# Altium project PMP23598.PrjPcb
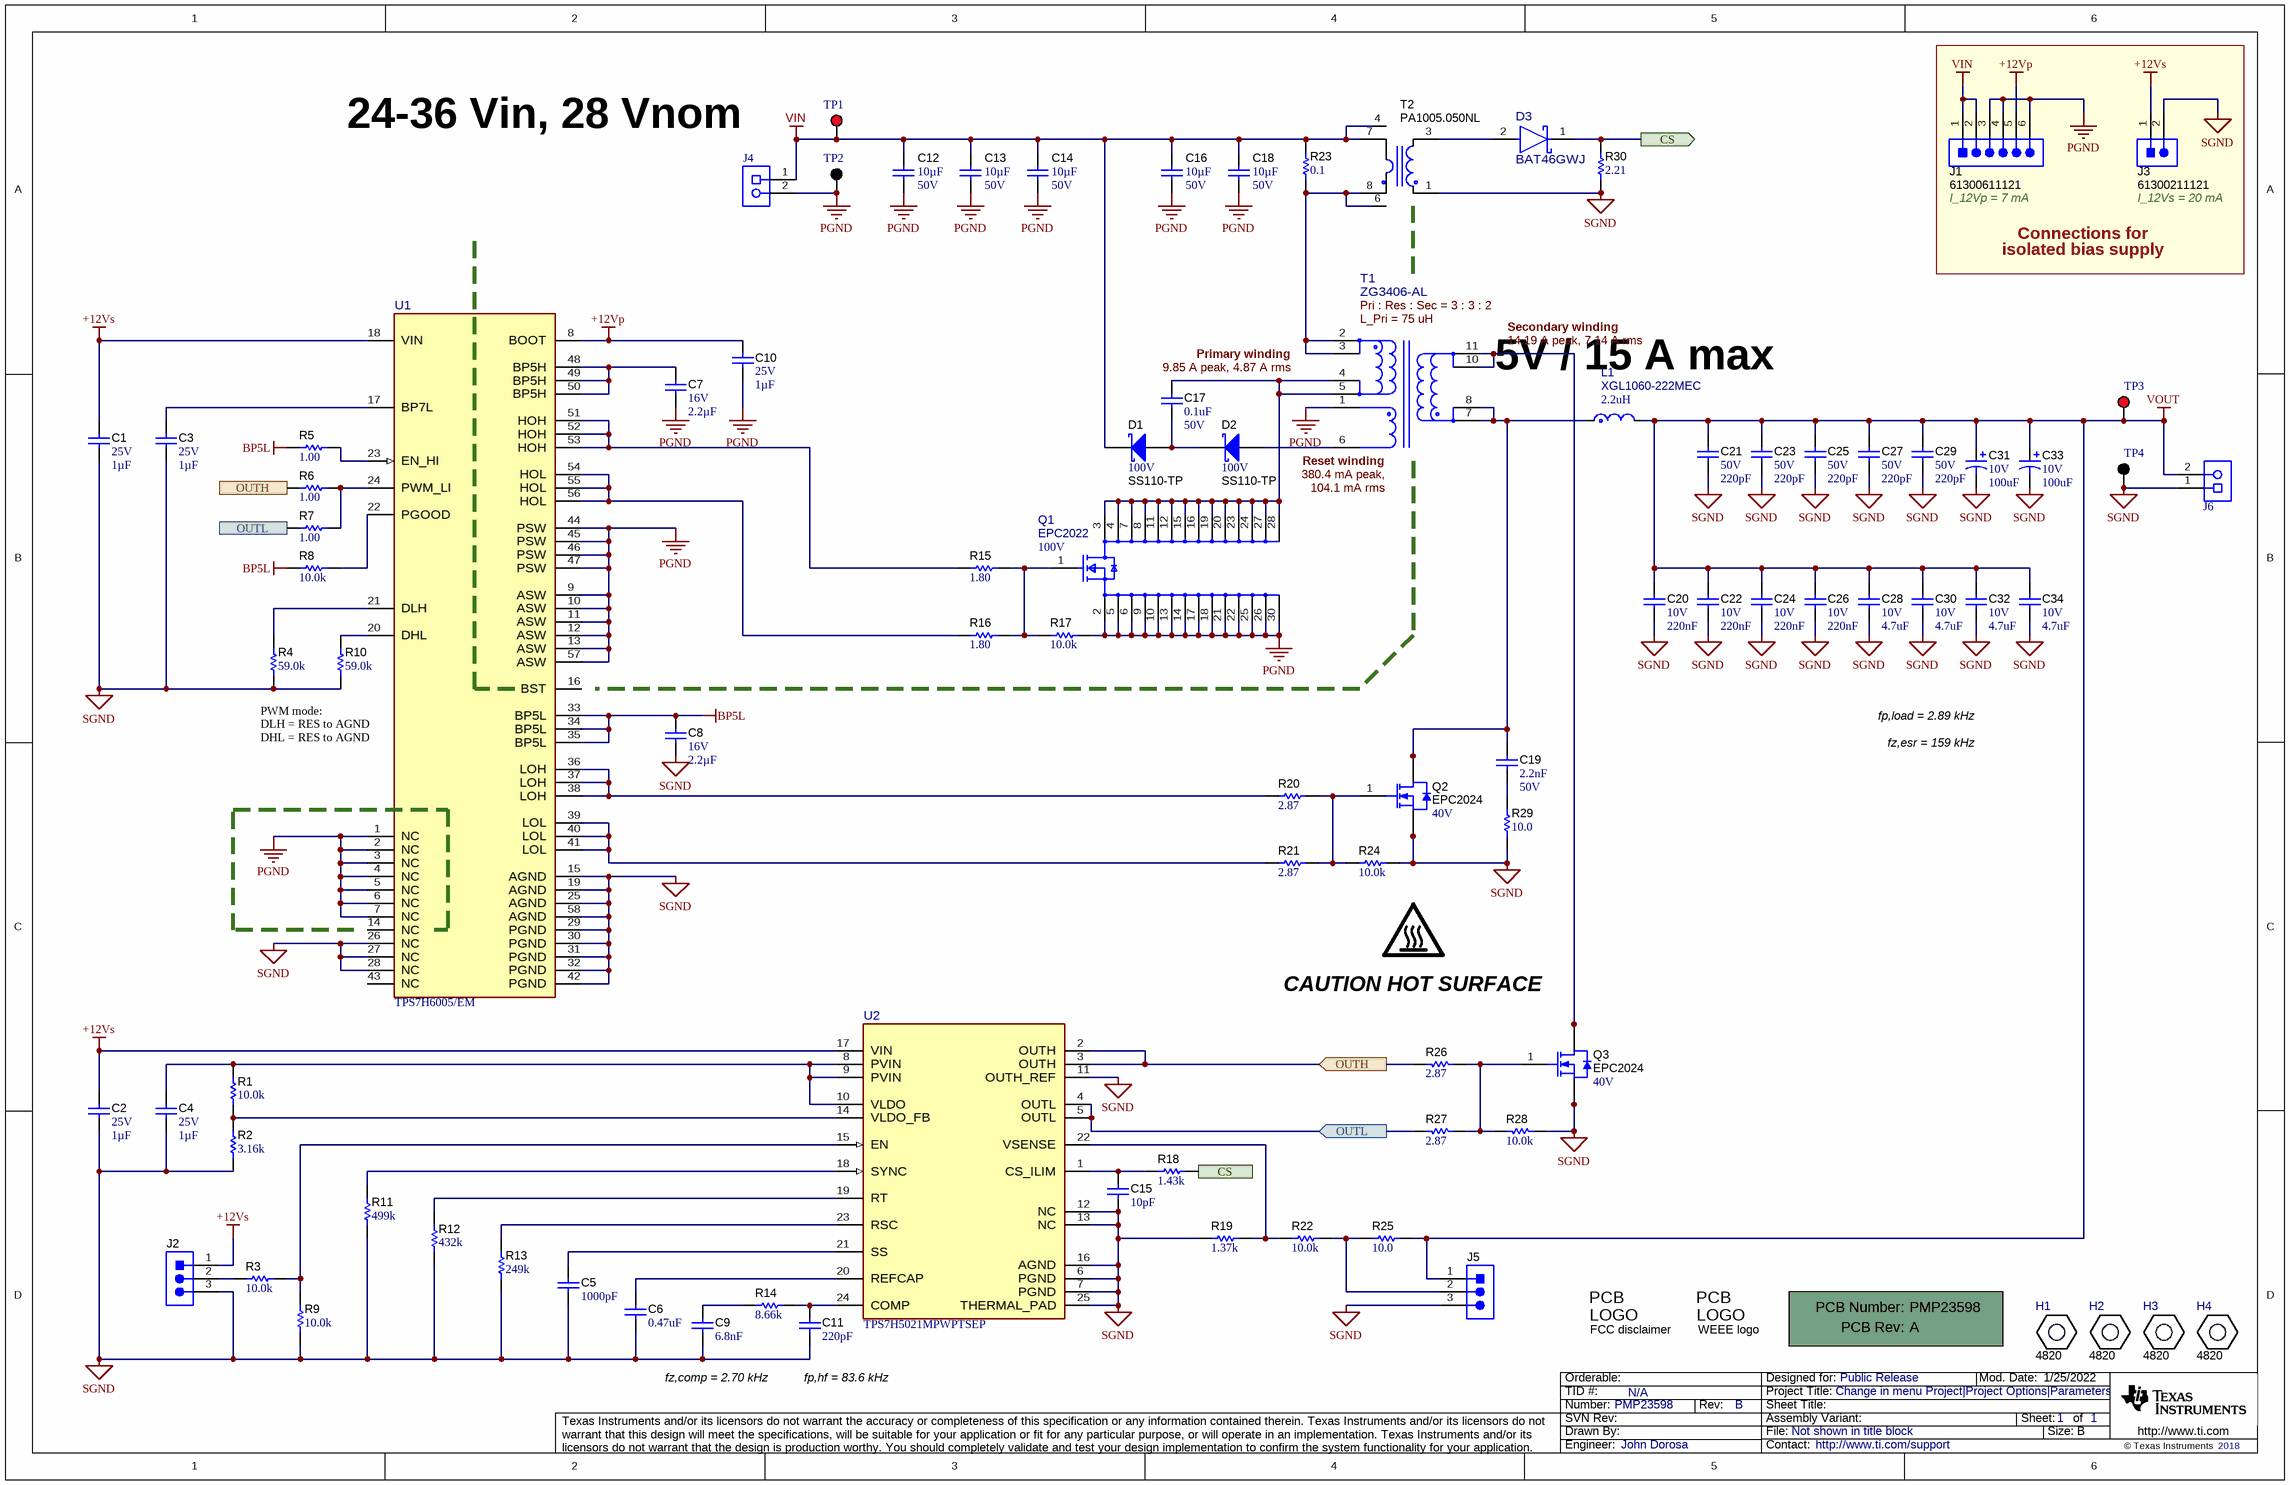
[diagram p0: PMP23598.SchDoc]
TID: N/A; TechSupport: http://www.ti.com/support; SCH_Rev: B; PRJ_Title: Change in menu Project|Project Options|Parameters; PRJ_Number: PMP23598; PRJ_Engineer: John Dorosa; PRJ_Customer: Public Release; PCB_Rev: A; PCB_Layout: John Dorosa; CopyrightYear: 2018
1 sheet, 93 parts. Net scope: flat (ports and power ports of the same name join across sheets).
Board file: PMP23598.PcbDoc

## Sheet PMP23598.SchDoc
size 431 x 279 mm; Date: Not shown in title block; ApprovedBy: Not shown in title block; CheckedBy: Not shown in title block; Author: Not shown in title block; CompanyName: Not shown in title block; Engineer: Not shown in title block; Organization: Not shown in title block; Address1: Not shown in title block; Address2: Not shown in title block; Address3: Not shown in title block; Address4: Not shown in title block; DocumentNumber: 1; Revision: Use project parameter SCH_Rev; SheetNumber: 1; SheetTotal: 1; PageSetup: Record=PageOptions¦CenterHorizontal=True¦CenterVertical=True¦PrintScale=1.00¦XCorrection=1.00¦YCorrection=1.00¦PrintKind=0¦BorderSize=5000000¦LeftOffset=0¦BottomOffset=0¦Orientation=2¦PaperLength=1000¦PaperWidth=1000¦Scale=100¦PaperSource=15¦PrintQuality=600¦MediaType=1¦DitherType=10¦PaperKind=Letter¦PrintScaleMode=1

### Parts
!PCB1  Printed Circuit Board  (value not drawn)  (mechanical)
C1  VDC_V: 25V  Cap_F: 1µF  [0603_HV]  (hidden comment: GRM188R71E105KA12D)
C2  VDC_V: 25V  Cap_F: 1µF  [0603_HV]  (hidden comment: GRM188R71E105KA12D)
C3  VDC_V: 25V  Cap_F: 1µF  [0603_HV]  (hidden comment: GRM188R71E105KA12D)
C4  VDC_V: 25V  Cap_F: 1µF  [0603_HV]  (hidden comment: GRM188R71E105KA12D)
C5  value 1000pF  [0603_HV]  (hidden comment: GRM188R71E102KA01D)
C6  value 0.47uF  [0603_HV]  (hidden comment: GCM188R71C474KA55D)
C7  VDC_V: 16V  Cap_F: 2.2µF  [0603_HV]  (hidden comment: GRM188Z71C225KE43)
C8  VDC_V: 16V  Cap_F: 2.2µF  [0603_HV]  (hidden comment: GRM188Z71C225KE43)
C9  Cap_F: 6.8nF  [0603_HV]  (hidden comment: GRM188R71E682KA01D)
C10  VDC_V: 25V  Cap_F: 1µF  [0603_HV]  (hidden comment: GRM188R71E105KA12D)
C11  Cap_F: 220pF  [0603_HV]  (hidden comment: GRM188R71H221KA01D)
C12  ValueDisplayed: 10µF  VDC_V: 50V  [1210_270]  (hidden comment: GCM32EL8EH106KA07L)
C13  ValueDisplayed: 10µF  VDC_V: 50V  [1210_270]  (hidden comment: GCM32EL8EH106KA07L)
C14  ValueDisplayed: 10µF  VDC_V: 50V  [1210_270]  (hidden comment: GCM32EL8EH106KA07L)
C15  ValueDisplayed: 10pF  [0603_HV]  (hidden comment: GCM1885C2A100JA16D)
C16  ValueDisplayed: 10µF  VDC_V: 50V  [1210_270]  (hidden comment: GCM32EL8EH106KA07L)
C17  value 0.1uF  VDC_V: 50V  [0805_HV]  (hidden comment: GRM21BR71H104KA01L)
C18  ValueDisplayed: 10µF  VDC_V: 50V  [1210_270]  (hidden comment: GCM32EL8EH106KA07L)
C19  Cap_F: 2.2nF  VDC_V: 50V  [0603_HV]  (hidden comment: GRM188R71H222KA01D)
C20  Value2: 10V  Cap_F: 220nF  [0805_HV]  (hidden comment: GRM216R71A224KC01D)
C21  VDC_V: 50V  ValueDisplayed: 220pF  [0402]  (hidden comment: GRM155R71H221KA01D)
C22  Value2: 10V  Cap_F: 220nF  [0805_HV]  (hidden comment: GRM216R71A224KC01D)
C23  VDC_V: 50V  ValueDisplayed: 220pF  [0402]  (hidden comment: GRM155R71H221KA01D)
C24  Value2: 10V  Cap_F: 220nF  [0805_HV]  (hidden comment: GRM216R71A224KC01D)
C25  VDC_V: 50V  ValueDisplayed: 220pF  [0402]  (hidden comment: GRM155R71H221KA01D)
C26  Value2: 10V  Cap_F: 220nF  [0805_HV]  (hidden comment: GRM216R71A224KC01D)
C27  VDC_V: 50V  ValueDisplayed: 220pF  [0402]  (hidden comment: GRM155R71H221KA01D)
C28  VDC_V: 10V  ValueDisplayed: 4.7uF  [1210]  (hidden comment: C1210C475K8RACTU)
C29  VDC_V: 50V  ValueDisplayed: 220pF  [0402]  (hidden comment: GRM155R71H221KA01D)
C30  VDC_V: 10V  ValueDisplayed: 4.7uF  [1210]  (hidden comment: C1210C475K8RACTU)
C31  VDC_V: 10V  ValueDisplayed: 100uF  [6032-15]  (hidden comment: T495U107K010ZTE150)
C32  VDC_V: 10V  ValueDisplayed: 4.7uF  [1210]  (hidden comment: C1210C475K8RACTU)
C33  VDC_V: 10V  ValueDisplayed: 100uF  [6032-15]  (hidden comment: T495U107K010ZTE150)
C34  VDC_V: 10V  ValueDisplayed: 4.7uF  [1210]  (hidden comment: C1210C475K8RACTU)
D1  SS110-TP  value 100V  [SMA]
D2  SS110-TP  value 100V  [SMA]
D3  BAT46GWJ  [FP-BAT46GWJ_SOD-123-MFG]
H1  4820  [KEYSTONE_4820]
H2  4820  [KEYSTONE_4820]
H3  4820  [KEYSTONE_4820]
H4  4820  [KEYSTONE_4820]
J1  61300611121  [WURTH_61300611121]
J2  61300311121  [WURTH_61300311121]  (value not drawn)
J3  61300211121  [WURTH_61300211121]
J4  ED120/2DS  [On-Shore_ED120_2DS]  (value not drawn)
J5  61300311121  [WURTH_61300311121]  (value not drawn)
J6  ED120/2DS  [On-Shore_ED120_2DS]  (value not drawn)
L1  XGL1060-222MEC  value 2.2uH  [FP-XGL1060-222MEC_SMD2-MFG]
Logo1  CAUTION HOT SURFACE  [IEC_HotSurface_Small]  (no BOM)
Logo2  FCC disclaimer  [FCC_disclaimer]  (no BOM)
Logo3  WEEE logo  [WEEE_Minimum]  (no BOM)
Q1  EPC2022  VdsMax_V: 100V  [FP-EPC2022_LGA30-MFG]
Q2  EPC2024  value 40V  [EPC2023]
Q3  EPC2024  value 40V  [EPC2023]
R1  ValueDisplayed: 10.0k  [0603_HV]  (hidden comment: CRCW060310K0FKEA)
R2  ValueDisplayed: 3.16k  [0603_HV]  (hidden comment: CRCW06033K16FKEA)
R3  ValueDisplayed: 10.0k  [0603_HV]  (hidden comment: CRCW060310K0FKEA)
R4  ValueDisplayed: 59.0k  [0603_HV]  (hidden comment: CRCW060359K0FKEA)
R5  ValueDisplayed: 1.00  [0603_HV]  (hidden comment: CRCW06031R00FKEA)
R6  ValueDisplayed: 1.00  [0603_HV]  (hidden comment: CRCW06031R00FKEA)
R7  ValueDisplayed: 1.00  [0603_HV]  (hidden comment: CRCW06031R00FKEA)
R8  ValueDisplayed: 10.0k  [0603_HV]  (hidden comment: RG1608P-103-B-T5)
R9  ValueDisplayed: 10.0k  [0603_HV]  (hidden comment: CRCW060310K0FKEA)
R10  ValueDisplayed: 59.0k  [0603_HV]  (hidden comment: CRCW060359K0FKEA)
R11  ValueDisplayed: 499k  [0603_HV]  (hidden comment: CRCW0603499KFKEA)
R12  ValueDisplayed: 432k  [0603_HV]  (hidden comment: CRCW0603432KFKEA)
R13  ValueDisplayed: 249k  [0603_HV]  (hidden comment: CRCW0603249KFKEA)
R14  ValueDisplayed: 8.66k  [0603_HV]  (hidden comment: CRCW06038K66FKEA)
R15  ValueDisplayed: 1.80  [0603_HV]  (hidden comment: CRCW06031R80FKEA)
R16  ValueDisplayed: 1.80  [0603_HV]  (hidden comment: CRCW06031R80FKEA)
R17  ValueDisplayed: 10.0k  [0603_HV]  (hidden comment: CRCW060310K0FKEA)
R18  ValueDisplayed: 1.43k  [0603_HV]  (hidden comment: CRCW06031K43FKEA)
R19  ValueDisplayed: 1.37k  [0603_HV]  (hidden comment: CRCW06031K37FKEA)
R20  ValueDisplayed: 2.87  [0603_HV]  (hidden comment: CRCW06032R87FKEA)
R21  ValueDisplayed: 2.87  [0603_HV]  (hidden comment: CRCW06032R87FKEA)
R22  ValueDisplayed: 10.0k  [0603_HV]  (hidden comment: CRCW060310K0FKEA)
R23  ValueDisplayed: 0.1  [1210]  (hidden comment: ERJ14RSJR10U)
R24  ValueDisplayed: 10.0k  [0603_HV]  (hidden comment: CRCW060310K0FKEA)
R25  ValueDisplayed: 10.0  [0603_HV]  (hidden comment: CRCW060310R0FKEA)
R26  ValueDisplayed: 2.87  [0603_HV]  (hidden comment: CRCW06032R87FKEA)
R27  ValueDisplayed: 2.87  [0603_HV]  (hidden comment: CRCW06032R87FKEA)
R28  ValueDisplayed: 10.0k  [0603_HV]  (hidden comment: CRCW060310K0FKEA)
R29  ValueDisplayed: 10.0  [1218]  (hidden comment: CRCW121810R0FKEK)
R30  ValueDisplayed: 2.21  [0805_HV1]  (hidden comment: CRCW08052R21FKEA)
T1  ZG3406-AL  [FP-ZG3406-AL_SMT_XFRMR_23MM37_20MM83-MFG]
T2  PA1005.050NL  [P82xx]
TP1  5010  [Keystone5010]  (value not drawn)
TP2  5011  [Keystone5011]  (value not drawn)
TP3  5010  [Keystone5010]  (value not drawn)
TP4  5011  [Keystone5011]  (value not drawn)
U1  TPS7H6005/EM  [DCA0056M-MFG]
U2  TPS7H5021MPWPTSEP  [PWP0024R-MFG]

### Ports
CS (in), CS (out), OUTH (in), OUTL (in)

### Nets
+12Vp: C10.1 J1.5 U1.8(BOOT)
+12Vs: C1.1 C2.1 J2.1 J3.1 U1.18(VIN) U2.17(VIN)
BP5L: C8.2 R5.2 R8.1 U1.33(BP5L) U1.34(BP5L) U1.35(BP5L)
PGND: C7.1 C10.2 C12.2 C13.2 C14.2 C16.2 C18.2 J1.3 J1.4 J1.6 J4.2 Q1.2(Source) Q1.5(Source) Q1.6(Source) Q1.9(Source) Q1.10(Source) Q1.13(Source) Q1.14(Source) Q1.17(Source) Q1.18(Source) Q1.21(Source) Q1.22(Source) Q1.25(Source) Q1.26(Source) Q1.30(Substrate) R17.2 T1.1 TP2.1 U1.1(NC) U1.2(NC) U1.3(NC) U1.4(NC) U1.5(NC) U1.6(NC) U1.7(NC) U1.9(ASW) U1.10(ASW) U1.11(ASW) U1.12(ASW) U1.13(ASW) U1.44(PSW) U1.45(PSW) U1.46(PSW) U1.47(PSW) U1.57(ASW)
SGND: C1.2 C2.2 C3.1 C4.2 C5.1 C6.2 C8.1 C9.2 C11.2 C15.2 C20.1 C21.2 C22.1 C23.2 C24.1 C25.2 C26.1 C27.2 C28.2 C29.2 C30.2 C31.2(-) C32.2 C33.2(-) C34.2 J2.3 J3.2 J5.3 J6.1 Q2.2(S) Q2.5(S) Q2.6(S) Q2.9(S) Q2.10(S) Q2.13(S) Q2.14(S) Q2.17(S) Q2.18(S) Q2.21(S) Q2.22(S) Q2.25(S) Q2.26(S) Q2.29(S) Q2.30(Substrate) Q3.2(S) Q3.5(S) Q3.6(S) Q3.9(S) Q3.10(S) Q3.13(S) Q3.14(S) Q3.17(S) Q3.18(S) Q3.21(S) Q3.22(S) Q3.25(S) Q3.26(S) Q3.29(S) Q3.30(Substrate) R2.2 R4.1 R9.1 R10.1 R11.1 R12.1 R13.1 R19.2 R24.2 R28.1 R29.1 R30.1 T2.1 TP4.1 U1.15(AGND) U1.19(AGND) U1.25(AGND) U1.26(NC) U1.27(NC) U1.28(NC) U1.29(PGND) U1.30(PGND) U1.31(PGND) U1.32(PGND) U1.42(PGND) U1.58(AGND) U2.6(PGND) U2.7(PGND) U2.11(OUTH_REF) U2.12(NC) U2.13(NC) U2.16(AGND) U2.25(THERMAL_PAD)
VIN: C12.1 C13.1 C14.1 C16.1 C18.1 D1.1(K) J1.1 J1.2 J4.1 R23.2 T2.4 T2.7 TP1.1
VOUT: C20.2 C21.1 C22.2 C23.1 C24.2 C25.1 C26.2 C27.1 C28.1 C29.1 C30.1 C31.1(+) C32.1 C33.1(+) C34.1 J5.1 J6.2 L1.2 R25.2 TP3.1
CS: D3.1(CATHODE) R18.2 R30.2 ; port CS
OUTH: R6.2 R26.2 U2.2(OUTH) U2.3(OUTH) ; port OUTH
OUTL: R7.2 R27.2 U2.4(OUTL) U2.5(OUTL) ; port OUTL
NetC3_2: C3.2 U1.17(BP7L)
NetC4_1: C4.1 R1.2 U2.8(PVIN) U2.9(PVIN) U2.10(VLDO)
NetC5_2: C5.2 U2.21(SS)
NetC6_1: C6.1 U2.20(REFCAP)
NetC7_2: C7.2 U1.48(BP5H) U1.49(BP5H) U1.50(BP5H)
NetC9_1: C9.1 R14.2
NetC11_1: C11.1 R14.1 U2.24(COMP)
NetC15_1: C15.1 R18.1 U2.1(CS_ILIM)
NetC17_1: C17.1 D1.2(A) D2.1(K)
NetC17_2: C17.2 Q1.3(Drain) Q1.4(Drain) Q1.7(Drain) Q1.8(Drain) Q1.11(Drain) Q1.12(Drain) Q1.15(Drain) Q1.16(Drain) Q1.19(Drain) Q1.20(Drain) Q1.23(Drain) Q1.24(Drain) Q1.27(Drain) Q1.28(Drain) T1.4 T1.5
NetC19_1: C19.1 L1.1 Q2.3(D) Q2.4(D) Q2.7(D) Q2.8(D) Q2.11(D) Q2.12(D) Q2.15(D) Q2.16(D) Q2.19(D) Q2.20(D) Q2.23(D) Q2.24(D) Q2.27(D) Q2.28(D) T1.7 T1.8
NetC19_2: C19.2 R29.2
NetD2_2: D2.2(A) T1.6
NetD3_2: D3.2(ANODE) T2.3
NetJ2_2: J2.2 R3.2
NetJ5_2: J5.2 R22.2 R25.1
NetQ1_1: Q1.1(Gate) R15.2 R16.2 R17.1
NetQ2_1: Q2.1(G) R20.2 R21.2 R24.1
NetQ3_1: Q3.1(G) R26.1 R27.1 R28.2
NetQ3_3: Q3.3(D) Q3.4(D) Q3.7(D) Q3.8(D) Q3.11(D) Q3.12(D) Q3.15(D) Q3.16(D) Q3.19(D) Q3.20(D) Q3.23(D) Q3.24(D) Q3.27(D) Q3.28(D) T1.10 T1.11
NetR1_1: R1.1 R2.1 U2.14(VLDO_FB)
NetR3_1: R3.1 R9.2 U2.15(EN)
NetR4_2: R4.2 U1.21(DLH)
NetR5_1: R5.1 U1.23(EN_HI)
NetR6_1: R6.1 R7.1 U1.24(PWM_LI)
NetR8_2: R8.2 U1.22(PGOOD)
NetR10_2: R10.2 U1.20(DHL)
NetR11_2: R11.2 U2.18(SYNC)
NetR12_2: R12.2 U2.19(RT)
NetR13_2: R13.2 U2.23(RSC)
NetR15_1: R15.1 U1.51(HOH) U1.52(HOH) U1.53(HOH)
NetR16_1: R16.1 U1.54(HOL) U1.55(HOL) U1.56(HOL)
NetR19_1: R19.1 R22.1 U2.22(VSENSE)
NetR20_1: R20.1 U1.36(LOH) U1.37(LOH) U1.38(LOH)
NetR21_1: R21.1 U1.39(LOL) U1.40(LOL) U1.41(LOL)
NetR23_1: R23.1 T1.2 T1.3 T2.6 T2.8

Not connected (* = marked no-connect by the designer): U1 14(NC) 16(BST) 43(NC)

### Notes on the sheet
- (near J4) 24-36 Vin, 28 Vnom
- I_12Vp = 7 mA
- Connections for
- I_12Vs = 20 mA
- isolated bias supply
- (near C17) 9.85 A peak, 4.87 A rms
- Primary winding
- (near T1) Pri : Res : Sec = 3 : 3 : 2
- (near T1) L_Pri = 75 uH
- 14.19 A peak, 7.14 A rms
- Secondary winding
- 5V / 15 A max
- (near T1) 380.4 mA peak,
- (near T1) Reset winding
- (near T1) 104.1 mA rms
- (near U1) PWM mode:
  DLH = RES to AGND
  DHL = RES to AGND
- fp,load = 2.89 kHz
- fz,esr = 159 kHz
- fz,comp = 2.70 kHz
- (near C11) fp,hf = 83.6 kHz

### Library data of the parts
!PCB1 = CMP-0003618-2: Manufacturer: Any; PartNumber: PMP23598
C1-C4 C10 = CMP-0007405-5: CAP, CERM, 1 uF, 25 V, +/- 10%, X7R, 0603; Manufacturer: MuRata; Cap_Case: 0603; AEC Category: Q200; Value: 1uF; SizeX_mm: 1.6; U/M: EA; Value1: Unknown; SizeAreaWB_mm2: 4.68; SizeY_mm: 0.8; TaMin_C: -55°C; SizeZ_mm: 1; Polarized: N; MFG_Status: TI_Obsolete; TaMax_C: 125°C; SizeArea_mm2: 1.28
C5 = CMP-0007402-5: CAP, CERM, 1000 pF, 25 V, +/- 10%, X7R, 0603; Manufacturer: MuRata; Value1: Unknown; VDC_V: 25V; TaMax_C: 125°C; Polarized: N; SizeArea_mm2: 1.28; Cap_Case: 0603; AEC Category: Q200; TaMin_C: -55°C; SizeX_mm: 1.6; U/M: EA; MFG_Status: TI_Obsolete; Cap_F: 1nF; SizeZ_mm: 1; SizeAreaWB_mm2: 4.68; SizeY_mm: 0.8
C6 = CMP-0007138-4: CAP, CERM, 0.47 uF, 16 V, +/- 10%, X7R, AEC-Q200 Grade 1, 0603; Manufacturer: MuRata; TaMin_C: -55°C; Polarized: N; SizeAreaWB_mm2: 4.68; Value1: Unknown; U/M: EA; TaMax_C: 125°C; SizeZ_mm: 1; SizeX_mm: 1.6; SizeY_mm: 0.8; Cap_Case: 0603; Value2: 16V; SizeArea_mm2: 1.28; AEC Qualified: Y; Cap_F: 470nF; AEC Category: Q200
C7 C8 = CMP-0007499-4: CAP, CERM, 2.2 uF, 16 V, +/- 10%, X7R, 0603; Manufacturer: MuRata; TaMin_C: -55°C; Polarized: N; SizeAreaWB_mm2: 4.68; Value1: Unknown; U/M: EA; Value: 2.2uF; TaMax_C: 125°C; SizeZ_mm: 1; SizeX_mm: 1.6; SizeY_mm: 0.8; Cap_Case: 0603; SizeArea_mm2: 1.28; AEC Category: Q200
C9 = CMP-0007427-5: CAP, CERM, 6800 pF, 25 V, +/- 10%, X7R, 0603; Manufacturer: MuRata; Value1: Unknown; MFG_Status: TI_Obsolete; SizeY_mm: 0.8; TaMin_C: -55°C; Value2: 25V; U/M: EA; SizeAreaWB_mm2: 4.68; SizeArea_mm2: 1.28; AEC Category: Q200; SizeZ_mm: 1; ValueDisplayed: 6800pF; Polarized: N; SizeX_mm: 1.6; TaMax_C: 125°C; Cap_Case: 0603; Value: 6800pF
C11 = CMP-0007442-5: CAP, CERM, 220 pF, 50 V, +/- 10%, X7R, 0603; Manufacturer: MuRata; TaMin_C: -55°C; Polarized: N; SizeAreaWB_mm2: 4.68; Value1: Unknown; U/M: EA; Value: 220pF; TaMax_C: 125°C; SizeZ_mm: 1; SizeX_mm: 1.6; SizeY_mm: 0.8; Cap_Case: 0603; Value2: 50V; SizeArea_mm2: 1.28; AEC Category: Q200
C12-C14 C16 C18 = CMP-0860266-1: CAP, CERM, 10 µF, 50 V,+/- 10%, X8L, AEC-Q200 Grade 0, 1210; Manufacturer: MuRata; Value: 10uF; U/M: EA; SizeY_mm: 2.5; Polarized: N; AEC Category: Q200; SizeZ_mm: 2.7; TaMin_C: -55°C; AEC Qualified: Y; TaMax_C: 150°C; Cap_Case: 1210; SizeArea_mm2: 8; SizeAreaWB_mm2: 14.7; AEC Grade: 0; SizeX_mm: 3.2
C15 = CMP-0084283-1: CAP, CERM, 10 pF, 100 V,+/- 5%, C0G/NP0, AEC-Q200 Grade 1, 0603; Manufacturer: MuRata; TaMax_C: 125°C; Cap_Case: 0603; Value2: 100V; SizeX_mm: 1.6; SizeY_mm: 0.8; SizeArea_mm2: 1.28; Polarized: N; AEC Category: Q200; SizeAreaWB_mm2: 4.68; AEC Qualified: Y; SizeZ_mm: 1; Value: 10pF; U/M: EA; TaMin_C: -55°C
C17 = CMP-0008349-2: CAP, CERM, 0.1 uF, 50 V, +/- 10%, X7R, 0805; Manufacturer: MuRata; TaMin_C: -55°C; Polarized: N; SizeAreaWB_mm2: 6.75; Value1: Unknown; U/M: EA; TaMax_C: 125°C; SizeZ_mm: 1.45; SizeX_mm: 2; SizeY_mm: 1.25; Cap_Case: 0805; SizeArea_mm2: 2.5; Cap_F: 100nF; AEC Category: Q200
C19 = CMP-0007443-4: CAP, CERM, 2200 pF, 50 V, +/- 10%, X7R, 0603; Manufacturer: MuRata; TaMin_C: -55°C; Polarized: N; SizeAreaWB_mm2: 4.68; Value1: Unknown; U/M: EA; Value: 2200pF; TaMax_C: 125°C; SizeZ_mm: 1; SizeX_mm: 1.6; SizeY_mm: 0.8; Cap_Case: 0603; SizeArea_mm2: 1.28; AEC Category: Q200
C20 C22 C24 C26 = CMP-0008137-2: CAP, CERM, 0.22 uF, 10 V, +/- 10%, X7R, 0805; Manufacturer: MuRata; TaMin_C: -55°C; Polarized: N; SizeAreaWB_mm2: 6.75; Value1: Unknown; U/M: EA; Value: 0.22uF; TaMax_C: 125°C; SizeZ_mm: 1.45; SizeX_mm: 2; SizeY_mm: 1.25; Cap_Case: 0805; SizeArea_mm2: 2.5; AEC Category: Q200
C21 C23 C25 C27 C29 = CMP-0006682-2: CAP, CERM, 220 pF, 50 V, +/- 10%, X7R, 0402; Manufacturer: MuRata; TaMin_C: -55°C; Polarized: N; SizeAreaWB_mm2: 3; Value1: Unknown; U/M: EA; Value: 220pF; TaMax_C: 125°C; SizeZ_mm: 0.6; SizeX_mm: 1; SizeY_mm: 0.5; AEC Category: Q200
C28 C30 C32 C34 = CMP-0009088-1: CAP, CERM, 4.7 uF, 10 V, +/- 10%, X7R, 1210; Manufacturer: Kemet; TaMin_C: -55°C; Polarized: N; SizeAreaWB_mm2: 14.7; Value1: Unknown; U/M: EA; Value: 4.7uF; TaMax_C: 125°C; SizeZ_mm: 1.35; SizeX_mm: 3.2; SizeY_mm: 2.5; SizeArea_mm2: 8; Cap_F: 4.7µF; AEC Category: Q200
C31 C33 = CMP-0011640-3: CAP, TA, 100 uF, 10 V, +/- 10%, 0.15 ohm, SMD; Manufacturer: Kemet; SizeAreaWB_mm2: 41.6; SizeX_mm: 6; MFG_Status: TI_Obsolete; TaMin_C: -55°C; ESR_ohm: 0.15; SizeZ_mm: 1.5; Value: 100uF; Cap_Case: U; U/M: EA; Polarized: Y; SizeArea_mm2: 19.2; TaMax_C: 125°C; AEC Category: Q200; SizeY_mm: 3.2; Cap_F: 100µF; CompType: Capacitor
D1 D2 = CMP-0028597-2: Diode, Schottky, 100 V, 1 A, SMA; Manufacturer: Micro Commercial Components; Value2: 0.85V; Vf_V: 850mV; AEC Category: Q101; SizeZ_mm: 2.87; SizeX_mm: 5.59; TJmax_C: 125°C; SizeArea_mm2: 16.3228; Green_Lifecycle: Not Set; AEC Qualified: N; SizeY_mm: 2.92; Io_A: 1A; SizeAreaWB_mm2: 37.3428; Green_REACh: Incomplete
D3 = CMP-0090343-1: Diode Schottky 100V 250mA (DC) Surface Mount SOD-123; Manufacturer: Nexperia; SizeZ_mm: 1.3mm; Peak Reverse Current: 2uA; TaMin_C: -55°C; Cap_F: 39pF; TJmax_C: 150°C; AEC Grade: Grade 0; Max Surge Forward Current: 2.5A; Standoff Height: 0mm; TaMax_C: +150°C; AEC Qualified: Yes
H1-H4 = CMP-0003652-1: Manufacturer: Keystone; CompType: Standoff
J1 = CMP-0054801-2: Header, 2.54 mm, 6x1, Gold, TH; Manufacturer: Wurth Elektronik; Cert_UL: Y; Gender: Male; Row_Count: 1; Shrouded: N; Pitch_mm: 2.54
J2 J5 = CMP-0054796-4: Header, 2.54 mm, 3x1, Gold, TH; Manufacturer: Wurth Elektronik; Green_REACh: Passed; CT: FALSE; CNHeader: TRUE; Green_Lifecycle: Active
J3 = CMP-0054794-2: Header, 2.54 mm, 2x1, Gold, TH; Manufacturer: Wurth Elektronik; Shrouded: N; Gender: Male; Green_REACh: Passed; Pitch_mm: 2.54; Green_Lifecycle: Active; Row_Count: 1; Cert_UL: Y
J4 J6 = CMP-0074910-1: Terminal Block, 5.08 mm, 2x1, Brass, TH; Manufacturer: On-Shore Technology; Cert_VDE: Y; CNHeader: False; Current_A: 15A; Green_Lifecycle: Not Set; Shrouded: N; Gender: Female; Green_REACh: Incomplete; Voltage_V: 300V; Row_Count: 1; Pitch_mm: 5.08; CT: True
L1 = CMP-0122785-1: 2.2 µH Shielded Molded Inductor 25.3 A 4.3mOhm Max Nonstandard; Manufacturer: Coilcraft; AEC Grade: Grade 1; AEC Qualified: Yes; DCR_ohm: 4.3m; Ind_H: 2.2µH; Irms: 25.3A; Isat: 12.6A; Material: Composite; SizeZ_mm: 6mm; Self Resonant Frequency: 25MHz; Shrouded: true; TaMax_C: +125°C; TaMin_C: -40°C; Test Frequency: 1MHz; Tolerance_%: 20%
Logo1 = CMP-0074837-2: IEC 61010-1 Hot Surface Warning; Manufacturer: Texas Instruments; CompType: IC; AEC Category: Q200; SymbolCreator: a0412235
Logo2 = CMP-0074847-1: FCC_disclaimer; Library Reference: Logo
Logo3 = CMP-0074769-1
Q1 = CMP-0047741-1: MOSFET N-Channel 100 V 90A (Ta) Surface Mount Die; Manufacturer: EPC; AEC Qualified: No; QgTyp_nC: 13nC @ 5V; Rdson45_ohm: 2.4m; SizeZ_mm: 0.795mm; Vgs_V: 6V; ChMode: False; Input Capacitace At Vds: 1400pF @ 50V; Number Of Channels: 1; Pulse Drain Current: 390A; Rthja Max: 42°C/W; Standoff Height: 0.08mm; Threshold Vgs Max: 2.5V; Threshold Vgs Min: 0.8V; TJmax_C: +150°C; Typ Forward Diode Voltage: 1.8V
Q2 Q3 = CMP-0000717-1: MOSFET, N-CH, 40 V, 90 A, 6.05x2.3mm; Alternate Manufacturer: None; Manufacturer: EPC; SizeZ_mm: 0.785; ChType: N; Value2: 18 nC; SizeX_mm: 2.3; SizeAreaWB_mm2: 34.615; SizeY_mm: 6.05; Vgs_V: 6V; QgTyp_nC: 18; SizeArea_mm2: 13.915; AEC Category: Q101; IdsMax_A: 90A; U/M: EA
R1 R3 R9 R17 R22 R24 R28 = CMP-0021998-4: RES, 10.0 k, 1%, 0.1 W, AEC-Q200 Grade 0, 0603; Manufacturer: Vishay-Dale; Power_W: 100mW; TempCo: 100 ppm/C; Value_Code: 10k0; Value: 10.0k; EIA_Code: E96; Res_ohm: 10k; SizeX_mm: 1.6; SizeY_mm: 0.8; SizeZ_mm: 1; Value2: 0.1W; SizeArea_mm2: 1.28; AEC Qualified: Y; VDC_V: 75V; AEC Category: Q200; AEC Grade: 0
R2 = CMP-0022373-4: RES, 3.16 k, 1%, 0.1 W, AEC-Q200 Grade 0, 0603; Manufacturer: Vishay-Dale; Power_W: 100mW; TempCo: 100 ppm/C; Value_Code: 3k16; Value: 3.16k; EIA_Code: E96; SizeX_mm: 1.6; SizeY_mm: 0.8; SizeZ_mm: 1; Value2: 0.1W; SizeArea_mm2: 1.28; AEC Qualified: Y; VDC_V: 75V; AEC Category: Q200; AEC Grade: 0
R4 R10 = CMP-0022507-4: RES, 59.0 k, 1%, 0.1 W, AEC-Q200 Grade 0, 0603; Manufacturer: Vishay-Dale; Power_W: 100mW; TempCo: 100 ppm/C; Value_Code: 59k0; Value: 59.0k; EIA_Code: E96; Res_ohm: 59k; SizeX_mm: 1.6; SizeY_mm: 0.8; SizeZ_mm: 1; Value2: 0.1W; SizeArea_mm2: 1.28; AEC Qualified: Y; VDC_V: 75V; AEC Category: Q200; AEC Grade: 0
R5-R7 = CMP-0022170-4: RES, 1.00, 1%, 0.1 W, AEC-Q200 Grade 0, 0603; Manufacturer: Vishay-Dale; Power_W: 100mW; TempCo: 100 ppm/C; Value_Code: 1R00; Value: 1.00; EIA_Code: E96; Res_ohm: 1; SizeX_mm: 1.6; SizeY_mm: 0.8; Value2: 0.1W; SizeArea_mm2: 1.28; AEC Qualified: Y; VDC_V: 75V; AEC Category: Q200; AEC Grade: 0
R8 = CMP-0023404-3: RES, 10.0 k, 0.1%, 0.1 W, 0603; Manufacturer: Susumu Co Ltd; Power_W: 100mW; TempCo: 25 ppm/C; Value_Code: 10k0; U/M: EA; Value: 10.0k; EIA_Code: E192; Res_ohm: 10k; SizeX_mm: 1.6; SizeY_mm: 0.8; SizeZ_mm: 1; Value2: 0.1W; SizeArea_mm2: 1.28; VDC_V: 75V; AEC Category: Q200
R11 = CMP-0022445-4: RES, 499 k, 1%, 0.1 W, AEC-Q200 Grade 0, 0603; Manufacturer: Vishay-Dale; Power_W: 100mW; TempCo: 100 ppm/C; Value: 499k; EIA_Code: E96; SizeX_mm: 1.6; SizeY_mm: 0.8; SizeZ_mm: 1; Value2: 0.1W; SizeArea_mm2: 1.28; AEC Qualified: Y; VDC_V: 75V; AEC Category: Q200; AEC Grade: 0
R12 = CMP-0022420-4: RES, 432 k, 1%, 0.1 W, AEC-Q200 Grade 0, 0603; Manufacturer: Vishay-Dale; Power_W: 100mW; TempCo: 100 ppm/C; Value: 432k; EIA_Code: E96; SizeX_mm: 1.6; SizeY_mm: 0.8; SizeZ_mm: 1; Value2: 0.1W; SizeArea_mm2: 1.28; AEC Qualified: Y; VDC_V: 75V; AEC Category: Q200; AEC Grade: 0
R13 = CMP-0022234-4: RES, 249 k, 1%, 0.1 W, AEC-Q200 Grade 0, 0603; Manufacturer: Vishay-Dale; Power_W: 100mW; TempCo: 100 ppm/C; Value: 249k; EIA_Code: E96; SizeX_mm: 1.6; SizeY_mm: 0.8; SizeZ_mm: 1; Value2: 0.1W; SizeArea_mm2: 1.28; AEC Qualified: Y; VDC_V: 75V; AEC Category: Q200; AEC Grade: 0
R14 = CMP-0022637-4: RES, 8.66 k, 1%, 0.1 W, AEC-Q200 Grade 0, 0603; Manufacturer: Vishay-Dale; Power_W: 100mW; TempCo: 100 ppm/C; Value_Code: 8k66; Value: 8.66k; EIA_Code: E96; SizeX_mm: 1.6; SizeY_mm: 0.8; SizeZ_mm: 1; Value2: 0.1W; SizeArea_mm2: 1.28; AEC Qualified: Y; VDC_V: 75V; AEC Category: Q200; AEC Grade: 0
R15 R16 = CMP-0022195-4: RES, 1.80, 1%, 0.1 W, AEC-Q200 Grade 0, 0603; Manufacturer: Vishay-Dale; Power_W: 100mW; TempCo: 100 ppm/C; Value_Code: 1R80; Value: 1.80; Res_ohm: 1.8; SizeX_mm: 1.6; SizeY_mm: 0.8; SizeZ_mm: 1; Value2: 0.1W; SizeArea_mm2: 1.28; AEC Qualified: Y; AEC Grade: 0; AEC Category: Q200
R18 = CMP-0022124-4: RES, 1.43 k, 1%, 0.1 W, AEC-Q200 Grade 0, 0603; Manufacturer: Vishay-Dale; Power_W: 100mW; TempCo: 100 ppm/C; Value_Code: 1k43; Value: 1.43k; EIA_Code: E96; SizeX_mm: 1.6; SizeY_mm: 0.8; SizeZ_mm: 1; Value2: 0.1W; SizeArea_mm2: 1.28; AEC Qualified: Y; VDC_V: 75V; AEC Category: Q200; AEC Grade: 0
R19 = CMP-0022122-4: RES, 1.37 k, 1%, 0.1 W, AEC-Q200 Grade 0, 0603; Manufacturer: Vishay-Dale; Power_W: 100mW; TempCo: 100 ppm/C; Value_Code: 1k37; Value: 1.37k; EIA_Code: E96; SizeX_mm: 1.6; SizeY_mm: 0.8; SizeZ_mm: 1; Value2: 0.1W; SizeArea_mm2: 1.28; AEC Qualified: Y; VDC_V: 75V; AEC Category: Q200; AEC Grade: 0
R20 R21 R26 R27 = CMP-0022317-4: RES, 2.87, 1%, 0.1 W, AEC-Q200 Grade 0, 0603; Manufacturer: Vishay-Dale; Power_W: 100mW; TempCo: 100 ppm/C; Value_Code: 2R87; Value: 2.87; EIA_Code: E96; SizeX_mm: 1.6; SizeY_mm: 0.8; SizeZ_mm: 1; Value2: 0.1W; SizeArea_mm2: 1.28; AEC Qualified: Y; VDC_V: 75V; AEC Category: Q200; AEC Grade: 0
R23 = CMP-0015326-3: RES, 0.1, 5%, 0.25 W, AEC-Q200 Grade 0, 1210; Manufacturer: Panasonic; Power_W: 250mW; TempCo: 200 ppm/C; SizeAreaWB_mm2: 14.7; Value_Code: R100; Value: 0.1; EIA_Code: E24; SizeX_mm: 3.2; SizeY_mm: 2.5; SizeZ_mm: 1.35; Value2: 0.25W; SizeArea_mm2: 8; AEC Qualified: Y; AEC Category: Q200; AEC Grade: 0
R25 = CMP-0022003-4: RES, 10.0, 1%, 0.1 W, AEC-Q200 Grade 0, 0603; Manufacturer: Vishay-Dale; Power_W: 100mW; TempCo: 100 ppm/C; Value_Code: 10R0; Value: 10.0; EIA_Code: E96; Res_ohm: 10; SizeX_mm: 1.6; SizeY_mm: 0.8; SizeZ_mm: 1; Value2: 0.1W; SizeArea_mm2: 1.28; AEC Qualified: Y; VDC_V: 75V; AEC Category: Q200; AEC Grade: 0
R29 = CMP-0015024-3: RES, 10.0, 1%, 1 W, AEC-Q200 Grade 0, 1218; Manufacturer: Vishay-Dale; Power_W: 1W; TempCo: 100 ppm/C; SizeAreaWB_mm2: 23.52; Value_Code: 10R0; Value: 10.0; EIA_Code: E96; Res_ohm: 10; SizeX_mm: 3.2; SizeY_mm: 4.6; SizeZ_mm: 0.6; SizeArea_mm2: 14.72; AEC Qualified: Y; VDC_V: 200V; AEC Category: Q200; AEC Grade: 0
R30 = CMP-0021145-3: RES, 2.21, 1%, 0.125 W, AEC-Q200 Grade 0, 0805; Manufacturer: Vishay-Dale; Power_W: 125mW; TempCo: 100 ppm/C; Value_Code: 2R21; Value: 2.21; EIA_Code: E96; SizeX_mm: 2; SizeY_mm: 1.25; SizeZ_mm: 1.45; Value2: 0.125W; SizeArea_mm2: 2.5; AEC Qualified: Y; VDC_V: 150V; AEC Category: Q200; AEC Grade: 0
T1 = CMP-0125914-1: TRANSFORMER; Manufacturer: Coilcraft; DCR_ohm: 7.4m; Ind_H: 40µH; Ns1toNp: 2:2:1; Rsec1_ohm: 2.5m; SizeZ_mm: 10.44mm; AEC Qualified: No; Voltage_Isolation_Vrms: 1.5kV
T2 = CMP-0030382-2: SMT Current Sense Tranformer; Manufacturer: Pulse Engineering; Rsec1_ohm: 1.5; CompType: Transformer
TP1 TP3 = CMP-0055147-2: Test Point, Multipurpose, Red, TH; Manufacturer: Keystone Electronics; CT: TRUE; ContactFinish: Silver; Green_Lifecycle: Active; CNHeader: FALSE; Green_REACh: Passed
TP2 TP4 = CMP-0055148-2: Test Point, Multipurpose, Black, TH; Manufacturer: Keystone Electronics; CNHeader: FALSE; ContactFinish: Silver; Green_REACh: Passed; Green_Lifecycle: Active; CT: TRUE
U1 = CMP-0120202-4: Manufacturer: Texas Instruments; SizeZ_mm: 1.2mm; Standoff Height: 0.05mm; AEC Category: Q200; CompType: IC
U2 = CMP-0122233-2: Radiation-Hardness-Assured 1-MHz Current Mode PWM Controller with Integrated Gate Driver; Manufacturer: Texas Instruments; SizeZ_mm: 1.2mm; AEC Qualified: No; Max Supply Voltage: 14V; Min Supply Voltage: 4.5V; Nominal Supply Current: 5-22mA; Number Of Outputs: 1; Standoff Height: 0.05mm; TJmax_C: +125°C; AEC Category: Q200; CompType: IC

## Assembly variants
001: not fitted H1 H2 H3 H4 R23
